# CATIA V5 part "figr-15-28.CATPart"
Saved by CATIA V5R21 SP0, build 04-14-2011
Part number: Part1
Bounding box of the stored display mesh (mm): x -61.282 to 61.282, y -26.72 to 26.72, z 0 to 45.75
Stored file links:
  D:\CATIA V5R21 E-RESOURCES\CATIA-V5R21\catia-v5r21-prt\c15-catia-v5r20-prt\c15-catia-v5r21-figr-15-28.CATPart
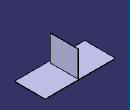
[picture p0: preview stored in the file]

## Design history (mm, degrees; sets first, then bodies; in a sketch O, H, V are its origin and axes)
SheetMetalParameters1: Thickness 0.75, BendRadius 1, KFactor 0.356492 {= log(min(100,max(20*SheetMetalParameters1.BendRadius,SheetMetalParameters1.Thickness)/SheetMetalParameters1.Thickness))/log(100)/2}, ReliefRadialLength 1, ReliefAxialLength 2, MinimumBendRadius 0
Body1 (main body)
  Sketch1 on xy-plane, origin (0, 0, 0), H (1, 0, 0), V (0, 1, 0)
    line L1 (61.282, 26.7197) -> (61.282, -26.7197)
    line L2 (61.282, -26.7197) -> (-61.282, -26.7197)
    line L3 (-61.282, -26.7197) -> (-61.282, 26.7197)
    line L4 (-61.282, 26.7197) -> (61.282, 26.7197)
    vertical: L1 V, L3 V
    horizontal: L2 H, L4 H
    equidistance: L1 L3 O, L2 L4 O
  Wall1: Thickness 0.75, Profile Sketch1
  Sketch2 on face of Wall1, origin (0, 0, 0.75), H (1, 0, 0), V (0, 1, 0)
    line L1 (1.9015, 25.4615) -> (1.9015, -22.9675)
    vertical: L1 V
  d_Extrude1: Extrude_Thickness 0.75, Extrude_Profile Sketch2, Extrude_StartLength 45, Extrude_EndLength 0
